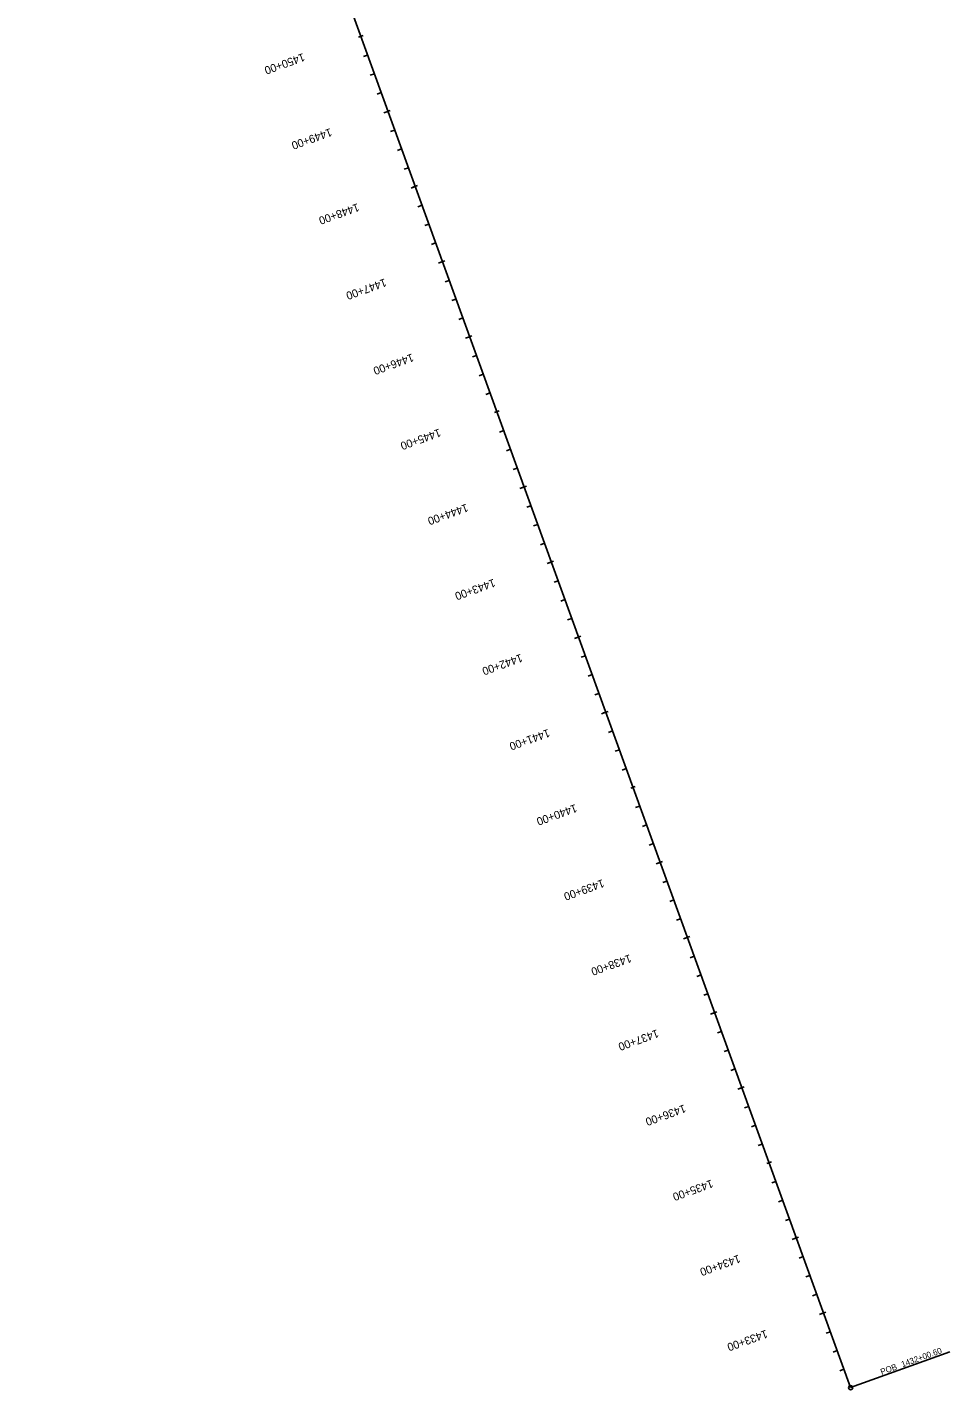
# Model space of a CAD drawing. Extents: x 21596470 to 21601942, y 8263806 to 8275912.
# Drawn here: x 21596601 to 21597756, y 8263806 to 8265512 of the extents above; entities that cross this region are included whole.
import ezdxf

# ---------------------------------------------------------------- set-up
doc = ezdxf.new("R2010")
doc.units = 0
for name, color, linetype in [('DsnShtInsideBorder', 7, 'Continuous'), ('Level 1', 7, 'Continuous'), ('Level 20', 7, 'Continuous'), ('wetNoteSoil', 7, 'Continuous')]:
    doc.layers.add(name, color=color, linetype=linetype)

msp = doc.modelspace()

# ---------------------------------------------------------------- linework, layer by layer
at = {"layer": 'DsnShtInsideBorder'}
for p in [(21597632.1, 8263808.8), (21597756.2, 8263853.8)]:
    msp.add_line(p, (21597756.2, 8263853.8), dxfattribs=at)
msp.add_circle((21597632.1, 8263808.8), 2.67, dxfattribs=at)
at = {"layer": 'Level 1'}
for p, q in [((21597016, 8265499.5), (21597021.8, 8265501.6)), ((21597053, 8265406.5), (21597047.8, 8265404.7)), ((21597087, 8265312.5), (21597081.9, 8265310.6)), ((21597121.1, 8265218.5), (21597116, 8265216.6)), ((21597155.2, 8265124.5), (21597150.1, 8265122.6)), ((21597186.4, 8265029.4), (21597192.1, 8265031.5)), ((21597223.3, 8264936.4), (21597218.2, 8264934.6)), ((21597257.4, 8264842.4), (21597252.3, 8264840.6)), ((21597291.5, 8264748.4), (21597286.4, 8264746.6)), ((21597325.6, 8264654.4), (21597320.4, 8264652.5)), ((21597356.8, 8264559.3), (21597362.5, 8264561.4)), ((21597393.7, 8264466.4), (21597388.6, 8264464.5)), ((21597427.8, 8264372.4), (21597422.7, 8264370.5)), ((21597461.9, 8264278.3), (21597456.7, 8264276.5)), ((21597496, 8264184.3), (21597490.8, 8264182.5)), ((21597527.2, 8264089.3), (21597532.9, 8264091.4)), ((21597564.1, 8263996.3), (21597559, 8263994.4)), ((21597598.2, 8263902.3), (21597593.1, 8263900.4))]:
    msp.add_line(p, q, dxfattribs=at)
at = {"layer": 'Level 20'}
for q in [(21596601.4, 8266652.3), (21596793.9, 8266121.3)]:
    msp.add_line((21597632.1, 8263808.8), q, dxfattribs=at)
at = {"layer": 'wetNoteSoil'}
for p, q in [((21597016, 8265499.5), (21597021.8, 8265501.6)), ((21597027.4, 8265477), (21597022.3, 8265475.2)), ((21597035.9, 8265453.5), (21597030.8, 8265451.7)), ((21597044.4, 8265430), (21597039.3, 8265428.2)), ((21597050.1, 8265405.5), (21597055.8, 8265407.6)), ((21597061.5, 8265383), (21597056.3, 8265381.2)), ((21597070, 8265359.5), (21597064.9, 8265357.7)), ((21597078.5, 8265336), (21597073.4, 8265334.2)), ((21597084.2, 8265311.5), (21597089.9, 8265313.6)), ((21597095.6, 8265289), (21597090.4, 8265287.1)), ((21597104.1, 8265265.5), (21597098.9, 8265263.6)), ((21597112.6, 8265242), (21597107.5, 8265240.1)), ((21597118.2, 8265217.5), (21597124, 8265219.5)), ((21597129.6, 8265195), (21597124.5, 8265193.1)), ((21597138.1, 8265171.5), (21597133, 8265169.6)), ((21597146.7, 8265148), (21597141.5, 8265146.1)), ((21597152.3, 8265123.4), (21597158.1, 8265125.5)), ((21597163.7, 8265101), (21597158.6, 8265099.1)), ((21597172.2, 8265077.5), (21597167.1, 8265075.6)), ((21597180.7, 8265054), (21597175.6, 8265052.1)), ((21597186.4, 8265029.4), (21597192.1, 8265031.5)), ((21597197.8, 8265007), (21597192.6, 8265005.1)), ((21597206.3, 8264983.5), (21597201.2, 8264981.6)), ((21597214.8, 8264960), (21597209.7, 8264958.1)), ((21597220.5, 8264935.4), (21597226.2, 8264937.5)), ((21597231.9, 8264912.9), (21597226.7, 8264911.1)), ((21597240.4, 8264889.4), (21597235.2, 8264887.6)), ((21597248.9, 8264865.9), (21597243.8, 8264864.1)), ((21597254.5, 8264841.4), (21597260.3, 8264843.5)), ((21597265.9, 8264818.9), (21597260.8, 8264817.1)), ((21597274.5, 8264795.4), (21597269.3, 8264793.6)), ((21597283, 8264771.9), (21597277.8, 8264770.1)), ((21597288.6, 8264747.4), (21597294.4, 8264749.5)), ((21597300, 8264724.9), (21597294.9, 8264723.1)), ((21597308.5, 8264701.4), (21597303.4, 8264699.6)), ((21597317.1, 8264677.9), (21597311.9, 8264676)), ((21597322.7, 8264653.4), (21597328.4, 8264655.4)), ((21597334.1, 8264630.9), (21597329, 8264629)), ((21597342.6, 8264607.4), (21597337.5, 8264605.5)), ((21597351.1, 8264583.9), (21597346, 8264582)), ((21597356.8, 8264559.3), (21597362.5, 8264561.4)), ((21597368.2, 8264536.9), (21597363, 8264535)), ((21597376.7, 8264513.4), (21597371.6, 8264511.5)), ((21597385.2, 8264489.9), (21597380.1, 8264488)), ((21597390.8, 8264465.3), (21597396.6, 8264467.4)), ((21597402.2, 8264442.9), (21597397.1, 8264441)), ((21597410.8, 8264419.4), (21597405.6, 8264417.5)), ((21597419.3, 8264395.9), (21597414.1, 8264394)), ((21597424.9, 8264371.3), (21597430.7, 8264373.4)), ((21597436.3, 8264348.9), (21597431.2, 8264347)), ((21597444.8, 8264325.4), (21597439.7, 8264323.5)), ((21597453.4, 8264301.9), (21597448.2, 8264300)), ((21597459, 8264277.3), (21597464.8, 8264279.4)), ((21597470.4, 8264254.8), (21597465.3, 8264253)), ((21597478.9, 8264231.3), (21597473.8, 8264229.5)), ((21597487.4, 8264207.8), (21597482.3, 8264206)), ((21597493.1, 8264183.3), (21597498.8, 8264185.4)), ((21597504.5, 8264160.8), (21597499.3, 8264159)), ((21597513, 8264137.3), (21597507.9, 8264135.5)), ((21597521.5, 8264113.8), (21597516.4, 8264112)), ((21597527.2, 8264089.3), (21597532.9, 8264091.4)), ((21597538.6, 8264066.8), (21597533.4, 8264065)), ((21597547.1, 8264043.3), (21597541.9, 8264041.4)), ((21597555.6, 8264019.8), (21597550.5, 8264017.9)), ((21597561.2, 8263995.3), (21597567, 8263997.3)), ((21597572.6, 8263972.8), (21597567.5, 8263970.9)), ((21597581.1, 8263949.3), (21597576, 8263947.4)), ((21597589.7, 8263925.8), (21597584.5, 8263923.9)), ((21597595.3, 8263901.2), (21597601.1, 8263903.3)), ((21597606.7, 8263878.8), (21597601.6, 8263876.9)), ((21597615.2, 8263855.3), (21597610.1, 8263853.4)), ((21597623.7, 8263831.8), (21597618.6, 8263829.9))]:
    msp.add_line(p, q, dxfattribs=at)

# ---------------------------------------------------------------- texts
at = {"layer": 'DsnShtInsideBorder'}
for s, p in [('1432+00.60', (21597697, 8263834.1)), ('POB ', (21597671, 8263824.7))]:
    msp.add_text(s, height=7.5, rotation=19.9238, dxfattribs=at).set_placement(p)
at = {"layer": 'Level 1'}
for s, p in [('1450+00', (21596946.7, 8265479.7)), ('1445+00', (21597117, 8265009.6)), ('1440+00', (21597287.4, 8264539.5)), ('1435+00', (21597457.8, 8264069.5))]:
    msp.add_text(s, height=10.02, rotation=199.9238, dxfattribs=at).set_placement(p)
at = {"layer": 'wetNoteSoil'}
for s, p in [('1450+00', (21596946.7, 8265479.7)), ('1449+00', (21596980.7, 8265385.7)), ('1448+00', (21597014.8, 8265291.7)), ('1447+00', (21597048.9, 8265197.6)), ('1446+00', (21597083, 8265103.6)), ('1445+00', (21597117, 8265009.6)), ('1444+00', (21597151.1, 8264915.6)), ('1443+00', (21597185.2, 8264821.6)), ('1442+00', (21597219.3, 8264727.6)), ('1441+00', (21597253.4, 8264633.6)), ('1440+00', (21597287.4, 8264539.5)), ('1439+00', (21597321.5, 8264445.5)), ('1438+00', (21597355.6, 8264351.5)), ('1437+00', (21597389.7, 8264257.5)), ('1436+00', (21597423.7, 8264163.5)), ('1435+00', (21597457.8, 8264069.5)), ('1434+00', (21597491.9, 8263975.5)), ('1433+00', (21597526, 8263881.4))]:
    msp.add_text(s, height=10.02, rotation=199.9238, dxfattribs=at).set_placement(p)

doc.saveas('drawing.dxf')
